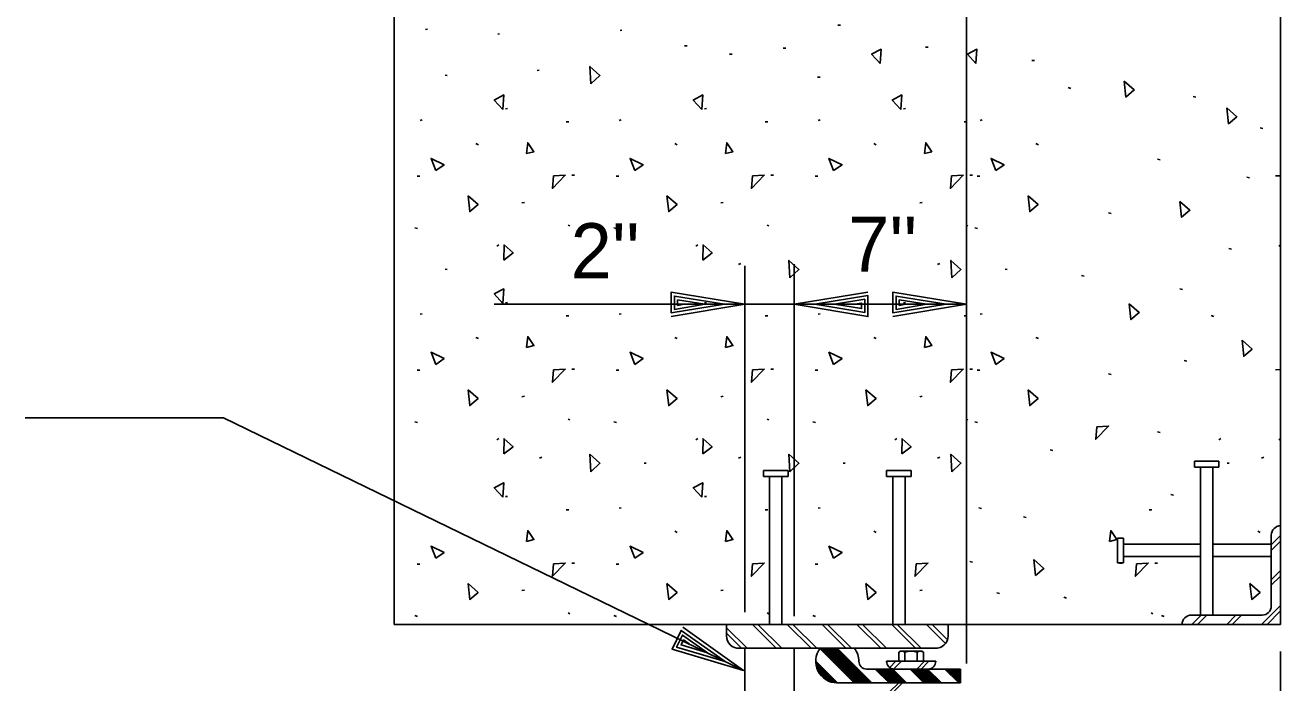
# Model space of a CAD drawing. Extents: x 0 to 53.3, y -2.9 to 37.3.
# Drawn here: x 9.83 to 14.079, y 17.432 to 19.657 of the extents above; entities that cross this region are included whole.
import ezdxf

# ---------------------------------------------------------------- set-up
doc = ezdxf.new("R2010")
doc.units = 0
for name, color, linetype in [('Level 2', 7, 'Continuous'), ('Level 22', 7, 'Continuous'), ('Level 25', 7, 'Continuous'), ('Level 3', 7, 'Continuous'), ('Level 44', 7, 'Continuous'), ('Level 50', 7, 'Continuous')]:
    doc.layers.add(name, color=color, linetype=linetype)

msp = doc.modelspace()

# ---------------------------------------------------------------- linework, layer by layer
at = {"layer": 'Level 2'}
for p, q in [((12.4113, 18.1506), (12.328, 18.1506)), ((12.828, 18.1506), (12.7447, 18.1506)), ((13.8697, 18.1818), (13.7863, 18.1818)), ((13.8697, 18.161), (13.7863, 18.161)), ((12.4113, 18.1298), (12.328, 18.1298)), ((12.828, 18.1298), (12.7447, 18.1298)), ((13.5259, 17.9214), (13.5259, 17.8381)), ((13.5468, 17.9214), (13.5468, 17.8381)), ((14.0155, 17.661), (13.7759, 17.661)), ((14.078, 17.6298), (11.078, 17.6298)), ((12.2655, 17.5489), (12.2655, 17.4006)), ((12.4322, 17.5489), (12.4322, 17.4006)), ((12.7915, 17.5388), (12.7859, 17.5356)), ((12.7859, 17.5049), (12.7859, 17.5356)), ((12.864, 17.5388), (12.7915, 17.5388)), ((12.8068, 17.5357), (12.8068, 17.5049)), ((12.8488, 17.5357), (12.8488, 17.5049)), ((12.864, 17.5388), (12.8696, 17.5356)), ((12.8696, 17.5049), (12.8696, 17.5356)), ((12.9947, 17.4787), (12.677, 17.4787)), ((12.9113, 17.5048), (12.7447, 17.5048)), ((12.7447, 17.5048), (12.7447, 17.5048)), ((12.9113, 17.5048), (12.7447, 17.5048)), ((12.7447, 17.5048), (12.7447, 17.5048)), ((12.8853, 17.4787), (12.7707, 17.4787)), ((12.8696, 17.5049), (12.7859, 17.5049)), ((12.9113, 17.5048), (12.9113, 17.5048)), ((12.9113, 17.5048), (12.9113, 17.5048)), ((12.9947, 17.4318), (12.9947, 17.4787)), ((12.9947, 17.4318), (12.578, 17.4318))]:
    msp.add_line(p, q, dxfattribs=at)
for centre, radius, start, end in [((14.078, 17.9318), 0.0313, 90, 180), ((14.0155, 17.6922), 0.0313, 270, 0), ((13.7759, 17.6297), 0.0313, 90, 180), ((12.2447, 17.5904), 0.0417, 180, 273.1798), ((12.9113, 17.5905), 0.0417, 266.8202, 0), ((12.578, 17.5047), 0.0729, 142.7557, 270.0041), ((12.578, 17.5047), 0.0729, 359.9959, 37.2443), ((12.7965, 17.5207), 0.0182, 55.489, 120.2876), ((12.828, 17.4661), 0.0727, 73.5034, 106.9816), ((12.859, 17.5207), 0.0182, 59.7124, 124.511), ((12.677, 17.5047), 0.026, 180, 270), ((12.7707, 17.5047), 0.026, 180, 270), ((12.8853, 17.5047), 0.026, 270, 0)]:
    msp.add_arc(centre, radius, start, end, dxfattribs=at)
at = {"layer": 'Level 22'}
for p, q in [((9.8296, 18.3281), (10.5009, 18.3281)), ((10.5009, 18.3281), (12.2612, 17.4739))]:
    msp.add_line(p, q, dxfattribs=at)
at = {"layer": 'Level 25'}
msp.add_line((12.909, 17.5489), (12.247, 17.5489), dxfattribs=at)
at = {"layer": 'Level 3'}
for p, q in [((11.078, 21.8798), (11.078, 17.6298)), ((14.078, 20.6298), (14.078, 17.6298)), ((12.328, 18.1506), (12.328, 18.1298)), ((12.4113, 18.1506), (12.4113, 18.1298)), ((12.7447, 18.1506), (12.7447, 18.1298)), ((12.828, 18.1506), (12.828, 18.1298)), ((13.7863, 18.1818), (13.7863, 18.161)), ((13.8072, 18.161), (13.8072, 17.661)), ((13.8488, 18.161), (13.8488, 17.661)), ((13.8697, 18.1818), (13.8697, 18.161)), ((12.3488, 18.1298), (12.3488, 17.6298)), ((12.3905, 18.1298), (12.3905, 17.6298)), ((12.7655, 18.1298), (12.7655, 17.6298)), ((12.8072, 18.1298), (12.8072, 17.6298)), ((13.5259, 17.9214), (13.5468, 17.9214)), ((13.5468, 17.9006), (13.8072, 17.9006)), ((13.8488, 17.9006), (14.0468, 17.9006)), ((14.0468, 17.9318), (14.0468, 17.6923)), ((13.5468, 17.8589), (13.8072, 17.8589)), ((13.8488, 17.8589), (14.0468, 17.8589)), ((13.5259, 17.8381), (13.5468, 17.8381)), ((12.203, 17.6298), (12.203, 17.5905)), ((12.953, 17.6298), (12.953, 17.5905))]:
    msp.add_line(p, q, dxfattribs=at)
for points in [[(14.0468, 17.8985), (14.078, 17.9298)], [(14.0468, 17.8796), (14.078, 17.9109)], [(14.0468, 17.7806), (14.078, 17.8119)], [(14.0468, 17.7618), (14.078, 17.793)], [(14.0137, 17.6298), (14.078, 17.694)], [(13.778, 17.6298), (13.8093, 17.661)], [(13.7968, 17.6298), (13.8281, 17.661)], [(13.8958, 17.6298), (13.9271, 17.661)], [(13.9147, 17.6298), (13.946, 17.661)], [(14.0325, 17.6298), (14.078, 17.6752)], [(12.2726, 17.5489), (12.203, 17.6185)], [(12.2534, 17.5492), (12.203, 17.5996)], [(12.3716, 17.5489), (12.2908, 17.6298)], [(12.3905, 17.5489), (12.3096, 17.6298)], [(12.4895, 17.5489), (12.4086, 17.6298)], [(12.5083, 17.5489), (12.4275, 17.6298)], [(12.6073, 17.5489), (12.5264, 17.6298)], [(12.6262, 17.5489), (12.5453, 17.6298)], [(12.7252, 17.5489), (12.6443, 17.6298)], [(12.7441, 17.5489), (12.6631, 17.6298)], [(12.843, 17.5489), (12.7621, 17.6298)], [(12.8619, 17.5489), (12.781, 17.6298)], [(12.9445, 17.5653), (12.88, 17.6298)], [(12.951, 17.5776), (12.8988, 17.6298)], [(12.6355, 17.4318), (12.5193, 17.548)], [(12.58, 17.5465), (12.5215, 17.5465)], [(12.585, 17.5415), (12.5265, 17.5415)], [(12.59, 17.5365), (12.5315, 17.5365)], [(12.595, 17.5315), (12.5365, 17.5315)], [(12.6, 17.5265), (12.5414, 17.5265)], [(12.605, 17.5215), (12.5464, 17.5215)], [(12.6099, 17.5165), (12.5514, 17.5165)], [(12.6149, 17.5115), (12.5563, 17.5115)], [(12.6945, 17.4318), (12.5775, 17.5489)], [(12.5785, 17.4318), (12.5051, 17.5053)], [(12.5084, 17.5019), (12.5052, 17.5019)], [(12.5133, 17.4969), (12.5053, 17.4969)], [(12.5183, 17.4919), (12.5064, 17.4919)], [(12.5233, 17.4869), (12.5076, 17.4869)], [(12.5283, 17.4819), (12.5094, 17.4819)], [(12.5332, 17.4769), (12.5113, 17.4769)], [(12.5382, 17.4719), (12.5137, 17.4719)], [(12.5431, 17.4669), (12.5163, 17.4669)], [(12.6198, 17.5065), (12.5613, 17.5065)], [(12.6248, 17.5015), (12.5663, 17.5015)], [(12.6298, 17.4965), (12.5713, 17.4965)], [(12.6348, 17.4915), (12.5762, 17.4915)], [(12.6398, 17.4865), (12.5812, 17.4865)], [(12.6448, 17.4815), (12.5861, 17.4815)], [(12.6498, 17.4765), (12.5911, 17.4765)], [(12.6547, 17.4715), (12.5961, 17.4715)], [(12.6597, 17.4665), (12.601, 17.4665)], [(12.7534, 17.4318), (12.7065, 17.4787)], [(12.7695, 17.4747), (12.7107, 17.4747)], [(12.7745, 17.4697), (12.7157, 17.4697)], [(12.7555, 17.4836), (12.7766, 17.5048)], [(12.8123, 17.4318), (12.7655, 17.4787)], [(12.7688, 17.4787), (12.7949, 17.5048)], [(12.8712, 17.4318), (12.8244, 17.4787)], [(12.8837, 17.4785), (12.8249, 17.4785)], [(12.8887, 17.4735), (12.8299, 17.4735)], [(12.8936, 17.4685), (12.8349, 17.4685)], [(12.8469, 17.4787), (12.8729, 17.5048)], [(12.8618, 17.4787), (12.8879, 17.5048)], [(12.9302, 17.4318), (12.8833, 17.4787)], [(12.9891, 17.4318), (12.9423, 17.4787)], [(12.9947, 17.476), (12.9463, 17.476)], [(12.9947, 17.471), (12.9513, 17.471)], [(12.9947, 17.466), (12.9563, 17.466)], [(12.5481, 17.4619), (12.5198, 17.4619)], [(12.553, 17.4569), (12.5233, 17.4569)], [(12.558, 17.4519), (12.5281, 17.4519)], [(12.563, 17.4469), (12.5335, 17.4469)], [(12.568, 17.4419), (12.5406, 17.4419)], [(12.5729, 17.4369), (12.5519, 17.4369)], [(12.5779, 17.4319), (12.5754, 17.4319)], [(12.6647, 17.4615), (12.606, 17.4615)], [(12.6697, 17.4565), (12.6109, 17.4565)], [(12.6746, 17.4515), (12.6159, 17.4515)], [(12.6796, 17.4465), (12.6209, 17.4465)], [(12.6846, 17.4415), (12.6258, 17.4415)], [(12.6896, 17.4365), (12.6308, 17.4365)], [(12.7795, 17.4647), (12.7207, 17.4647)], [(12.7845, 17.4597), (12.7257, 17.4597)], [(12.7894, 17.4547), (12.7306, 17.4547)], [(12.7944, 17.4497), (12.7356, 17.4497)], [(12.7994, 17.4447), (12.7406, 17.4447)], [(12.8044, 17.4397), (12.7456, 17.4397)], [(12.8093, 17.4347), (12.7506, 17.4347)], [(12.755, 17.4011), (12.7862, 17.4324)], [(12.7671, 17.4006), (12.7984, 17.4318)], [(12.8986, 17.4635), (12.8399, 17.4635)], [(12.9036, 17.4585), (12.8449, 17.4585)], [(12.9085, 17.4535), (12.8499, 17.4535)], [(12.9135, 17.4485), (12.8549, 17.4485)], [(12.9185, 17.4435), (12.8598, 17.4435)], [(12.9235, 17.4385), (12.8648, 17.4385)], [(12.9285, 17.4335), (12.8698, 17.4335)], [(12.9947, 17.461), (12.9613, 17.461)], [(12.9947, 17.456), (12.9663, 17.456)], [(12.9947, 17.451), (12.9713, 17.451)], [(12.9947, 17.446), (12.9763, 17.446)], [(12.9947, 17.441), (12.9813, 17.441)], [(12.9947, 17.436), (12.9863, 17.436)]]:
    msp.add_lwpolyline(points, dxfattribs=at)
at = {"layer": 'Level 44'}
for p, q in [((11.1844, 19.642), (11.191, 19.6432)), ((11.8428, 19.6388), (11.8494, 19.64)), ((12.5795, 19.6565), (12.5885, 19.6565)), ((11.4288, 19.6261), (11.4355, 19.6273)), ((12.0615, 19.586), (12.0705, 19.586)), ((12.2136, 19.5578), (12.2226, 19.5578)), ((12.3948, 19.579), (12.4038, 19.579)), ((12.8765, 19.5825), (12.8855, 19.5825)), ((13.2369, 19.5367), (13.2459, 19.5367)), ((11.2509, 19.487), (11.2582, 19.4864)), ((11.5625, 19.5025), (11.5691, 19.5037)), ((12.5107, 19.4803), (12.5197, 19.4803)), ((13.3593, 19.4451), (13.3683, 19.4426)), ((13.7823, 19.4149), (13.7913, 19.4124)), ((11.1667, 19.3345), (11.1734, 19.3357)), ((11.4556, 19.3735), (11.4622, 19.374)), ((11.8401, 19.3345), (11.8467, 19.3357)), ((12.1289, 19.3735), (12.1356, 19.374)), ((12.5134, 19.3345), (12.5201, 19.3357)), ((12.8022, 19.3735), (12.8089, 19.374)), ((13.0617, 19.3345), (13.0684, 19.3357)), ((11.6607, 19.3289), (11.6697, 19.3289)), ((12.3341, 19.3289), (12.3431, 19.3289)), ((13.0074, 19.3289), (13.0164, 19.3289)), ((14.0089, 19.309), (14.0179, 19.3065)), ((11.3554, 19.256), (11.3634, 19.252)), ((12.0287, 19.256), (12.0367, 19.252)), ((12.7021, 19.256), (12.7101, 19.252)), ((13.2504, 19.256), (13.2584, 19.252)), ((13.6614, 19.2031), (13.6704, 19.2006)), ((11.1561, 19.1454), (11.1651, 19.1454)), ((11.6801, 19.1485), (11.6886, 19.1485)), ((11.8294, 19.1454), (11.8384, 19.1454)), ((12.3534, 19.1485), (12.3619, 19.1485)), ((12.5027, 19.1454), (12.5117, 19.1454)), ((13.0267, 19.1485), (13.0352, 19.1485)), ((13.0511, 19.1454), (13.0601, 19.1454)), ((13.9635, 19.1427), (13.9725, 19.1402)), ((11.5104, 19.0554), (11.5191, 19.0569)), ((12.1837, 19.0554), (12.1924, 19.0569)), ((12.8571, 19.0554), (12.8657, 19.0569)), ((13.4953, 19.0217), (13.5043, 19.0192)), ((11.1489, 18.9709), (11.1579, 18.9684)), ((11.6669, 18.9799), (11.6734, 18.9774)), ((11.8222, 18.9709), (11.8312, 18.9684)), ((12.3402, 18.9799), (12.3467, 18.9774)), ((13.0136, 18.9799), (13.0201, 18.9774)), ((13.0439, 18.9709), (13.0529, 18.9684)), ((11.4256, 18.9092), (11.4331, 18.9137)), ((12.0989, 18.9092), (12.1064, 18.9137)), ((14.0717, 18.9092), (14.0792, 18.9137)), ((13.9031, 18.9007), (13.9121, 18.8982)), ((11.2509, 18.8312), (11.2582, 18.8305)), ((12.2441, 18.8472), (12.2512, 18.8505)), ((12.9174, 18.8472), (12.9246, 18.8505)), ((13.1459, 18.8312), (13.1532, 18.8305)), ((13.4046, 18.81), (13.4136, 18.8075)), ((13.737, 18.7646), (13.746, 18.7621)), ((11.4556, 18.7177), (11.4622, 18.7182)), ((12.1289, 18.7177), (12.1356, 18.7182)), ((12.8022, 18.7177), (12.8089, 18.7182)), ((11.1667, 18.6787), (11.1734, 18.6799)), ((11.6607, 18.673), (11.6697, 18.673)), ((11.8401, 18.6787), (11.8467, 18.6799)), ((12.3341, 18.673), (12.3431, 18.673)), ((12.5134, 18.6787), (12.5201, 18.6799)), ((13.0074, 18.673), (13.0164, 18.673)), ((13.0617, 18.6787), (13.0684, 18.6799)), ((13.8427, 18.6739), (13.8517, 18.6714)), ((11.3554, 18.6002), (11.3634, 18.5962)), ((12.0287, 18.6002), (12.0367, 18.5962)), ((12.7021, 18.6002), (12.7101, 18.5962)), ((13.2504, 18.6002), (13.2584, 18.5962)), ((11.1561, 18.4895), (11.1651, 18.4895)), ((11.6801, 18.4927), (11.6886, 18.4927)), ((11.8294, 18.4895), (11.8384, 18.4895)), ((12.3534, 18.4927), (12.3619, 18.4927)), ((12.5027, 18.4895), (12.5117, 18.4895)), ((13.0267, 18.4927), (13.0352, 18.4927)), ((13.0511, 18.4895), (13.0601, 18.4895)), ((13.7521, 18.5226), (13.7611, 18.5201)), ((13.4953, 18.4773), (13.5043, 18.4748)), ((11.5104, 18.3995), (11.5191, 18.401)), ((12.1837, 18.3995), (12.1924, 18.401)), ((12.8571, 18.3995), (12.8657, 18.401)), ((11.6669, 18.324), (11.6734, 18.3215)), ((12.3402, 18.324), (12.3467, 18.3215)), ((13.0136, 18.324), (13.0201, 18.3215)), ((11.1489, 18.315), (11.1579, 18.3125)), ((11.8222, 18.315), (11.8312, 18.3125)), ((12.4956, 18.315), (12.5046, 18.3125)), ((13.0439, 18.315), (13.0529, 18.3125)), ((13.6614, 18.2807), (13.6704, 18.2782)), ((11.4256, 18.2534), (11.4331, 18.2579)), ((12.0989, 18.2534), (12.1064, 18.2579)), ((12.7722, 18.2534), (12.7797, 18.2579)), ((13.8689, 18.2534), (13.8764, 18.2579)), ((14.0717, 18.2534), (14.0792, 18.2579)), ((11.5707, 18.1914), (11.5779, 18.1947)), ((12.2441, 18.1914), (12.2512, 18.1947)), ((12.9174, 18.1914), (12.9246, 18.1947)), ((13.2989, 18.2202), (13.3079, 18.2177)), ((14.0141, 18.1914), (14.0212, 18.1947)), ((11.9242, 18.1754), (11.9316, 18.1747)), ((12.5976, 18.1754), (12.6049, 18.1747)), ((13.897, 18.1754), (13.9043, 18.1747)), ((11.4556, 18.0619), (11.4622, 18.0624)), ((12.1289, 18.0619), (12.1356, 18.0624)), ((13.7068, 18.069), (13.7158, 18.0665)), ((11.8401, 18.0229), (11.8467, 18.024)), ((12.5134, 18.0229), (12.5201, 18.024)), ((13.0572, 18.0236), (13.0662, 18.0211)), ((11.6607, 18.0172), (11.6697, 18.0172)), ((12.3341, 18.0172), (12.3431, 18.0172)), ((13.2083, 17.9934), (13.2173, 17.9909)), ((13.6335, 18.0172), (13.6425, 18.0172)), ((12.0287, 17.9444), (12.0367, 17.9404)), ((12.7021, 17.9444), (12.7101, 17.9404)), ((14.0015, 17.9444), (14.0095, 17.9404)), ((11.1561, 17.8337), (11.1651, 17.8337)), ((11.6801, 17.8369), (11.6886, 17.8369)), ((11.8294, 17.8337), (11.8384, 17.8337)), ((12.5027, 17.8337), (12.5117, 17.8337)), ((13.027, 17.8421), (13.036, 17.8396)), ((13.5334, 17.8369), (13.5419, 17.8369)), ((13.6528, 17.8369), (13.6613, 17.8369)), ((11.5104, 17.7437), (11.5191, 17.7452)), ((12.1837, 17.7437), (12.1924, 17.7452)), ((12.8571, 17.7437), (12.8657, 17.7452)), ((13.1176, 17.7363), (13.1266, 17.7338)), ((13.3442, 17.7212), (13.3532, 17.7187)), ((11.1489, 17.6592), (11.1579, 17.6567)), ((11.6669, 17.6682), (11.6734, 17.6657)), ((11.8222, 17.6592), (11.8312, 17.6567)), ((12.3402, 17.6682), (12.3467, 17.6657)), ((12.4956, 17.6592), (12.5046, 17.6567)), ((13.6397, 17.6682), (13.6462, 17.6657)), ((13.6756, 17.6592), (13.6846, 17.6567))]:
    msp.add_line(p, q, dxfattribs=at)
for points in [[(12.7228, 19.5262), (12.6943, 19.5582), (12.7262, 19.5752)], [(13.047, 19.5262), (13.0185, 19.5582), (13.0504, 19.5752)], [(11.7441, 19.4577), (11.7749, 19.4862), (11.7407, 19.5167)], [(13.5489, 19.4671), (13.583, 19.4372), (13.5547, 19.4134)], [(11.4459, 19.3712), (11.4174, 19.4032), (11.4492, 19.4202)], [(12.1192, 19.3712), (12.0907, 19.4032), (12.1226, 19.4202)], [(12.7926, 19.3712), (12.7641, 19.4032), (12.7959, 19.4202)], [(13.8963, 19.3763), (13.9305, 19.3465), (13.9021, 19.3227)], [(11.5261, 19.2222), (11.5307, 19.2587), (11.5512, 19.2282)], [(12.1994, 19.2222), (12.2041, 19.2587), (12.2246, 19.2282)], [(12.8727, 19.2222), (12.8774, 19.2587), (12.8979, 19.2282)], [(11.2191, 19.1649), (11.2032, 19.2057), (11.2474, 19.1842)], [(11.8924, 19.1649), (11.8766, 19.2057), (11.9207, 19.1842)], [(12.5657, 19.1649), (12.5499, 19.2057), (12.5941, 19.1842)], [(13.1141, 19.1649), (13.0982, 19.2057), (13.1424, 19.1842)], [(11.6176, 19.1464), (11.6576, 19.1485), (11.6142, 19.1042)], [(12.2909, 19.1464), (12.3309, 19.1485), (12.2876, 19.1042)], [(12.9642, 19.1464), (13.0042, 19.1485), (12.9609, 19.1042)], [(11.3284, 19.0794), (11.3626, 19.0495), (11.3342, 19.0257)], [(12.0017, 19.0794), (12.0359, 19.0495), (12.0076, 19.0257)], [(13.2234, 19.0794), (13.2576, 19.0495), (13.2292, 19.0257)], [(13.737, 19.0601), (13.7712, 19.0303), (13.7429, 19.0065)], [(11.4492, 18.862), (11.4812, 18.8862), (11.4506, 18.9134)], [(12.1226, 18.862), (12.1546, 18.8862), (12.1239, 18.9134)], [(12.4174, 18.8019), (12.4482, 18.8304), (12.4141, 18.8609)], [(12.9657, 18.8019), (12.9966, 18.8304), (12.9624, 18.8609)], [(11.4459, 18.7154), (11.4174, 18.7474), (11.4492, 18.7644)], [(13.5658, 18.714), (13.6, 18.6842), (13.5717, 18.6603)], [(11.5261, 18.5664), (11.5307, 18.6029), (11.5512, 18.5724)], [(12.1994, 18.5664), (12.2041, 18.6029), (12.2246, 18.5724)], [(12.8727, 18.5664), (12.8774, 18.6029), (12.8979, 18.5724)], [(13.9478, 18.5904), (13.9819, 18.5606), (13.9536, 18.5367)], [(11.2191, 18.509), (11.2032, 18.5499), (11.2474, 18.5284)], [(11.8924, 18.509), (11.8766, 18.5499), (11.9207, 18.5284)], [(12.5657, 18.509), (12.5499, 18.5499), (12.5941, 18.5284)], [(13.1141, 18.509), (13.0982, 18.5499), (13.1424, 18.5284)], [(11.6176, 18.4905), (11.6576, 18.4927), (11.6142, 18.4484)], [(12.2909, 18.4905), (12.3309, 18.4927), (12.2876, 18.4484)], [(12.9642, 18.4905), (13.0042, 18.4927), (12.9609, 18.4484)], [(11.3284, 18.4235), (11.3626, 18.3937), (11.3342, 18.3699)], [(12.0017, 18.4235), (12.0359, 18.3937), (12.0076, 18.3699)], [(12.6751, 18.4235), (12.7092, 18.3937), (12.6809, 18.3699)], [(13.2234, 18.4235), (13.2576, 18.3937), (13.2292, 18.3699)], [(13.456, 18.2983), (13.496, 18.3004), (13.4527, 18.2561)], [(11.4492, 18.2062), (11.4812, 18.2304), (11.4506, 18.2575)], [(12.1226, 18.2062), (12.1546, 18.2304), (12.1239, 18.2575)], [(12.7959, 18.2062), (12.8279, 18.2304), (12.7972, 18.2575)], [(11.7441, 18.146), (11.7749, 18.1745), (11.7407, 18.205)], [(12.4174, 18.146), (12.4482, 18.1745), (12.4141, 18.205)], [(12.9657, 18.146), (12.9966, 18.1745), (12.9624, 18.205)], [(11.4459, 18.0595), (11.4174, 18.0915), (11.4492, 18.1085)], [(12.1192, 18.0595), (12.0907, 18.0915), (12.1226, 18.1085)], [(11.5261, 17.9105), (11.5307, 17.947), (11.5512, 17.9165)], [(12.1994, 17.9105), (12.2041, 17.947), (12.2246, 17.9165)], [(13.4988, 17.9105), (13.5035, 17.947), (13.524, 17.9165)], [(11.2191, 17.8532), (11.2032, 17.894), (11.2474, 17.8725)], [(11.8924, 17.8532), (11.8766, 17.894), (11.9207, 17.8725)], [(12.5657, 17.8532), (12.5499, 17.894), (12.5941, 17.8725)], [(13.2431, 17.8487), (13.2773, 17.8189), (13.249, 17.7951)], [(11.6176, 17.8347), (11.6576, 17.8369), (11.6142, 17.7925)], [(12.2909, 17.8347), (12.3309, 17.8369), (12.2876, 17.7925)], [(12.8448, 17.8347), (12.8848, 17.8369), (12.8414, 17.7925)], [(13.5903, 17.8347), (13.6303, 17.8369), (13.587, 17.7925)], [(11.3284, 17.7677), (11.3626, 17.7379), (11.3342, 17.714)], [(12.0017, 17.7677), (12.0359, 17.7379), (12.0076, 17.714)], [(12.6751, 17.7677), (12.7092, 17.7379), (12.6809, 17.714)], [(13.9745, 17.7677), (14.0087, 17.7379), (13.9803, 17.714)]]:
    msp.add_lwpolyline(points, close=True, dxfattribs=at)
for points in [[(14.0609, 19.1464), (14.078, 19.1473)], [(14.0609, 18.4905), (14.078, 18.4915)]]:
    msp.add_lwpolyline(points, dxfattribs=at)
at = {"layer": 'Level 50'}
for p, q in [((13.0155, 17.4978), (13.0155, 21.1768)), ((12.2655, 17.6711), (12.2655, 18.8426)), ((12.4322, 17.6578), (12.4322, 18.8485)), ((12.2655, 18.7123), (11.4165, 18.7123)), ((12.1962, 18.7123), (12.1962, 18.7123)), ((12.4322, 18.7123), (12.2655, 18.7123)), ((12.2655, 18.7123), (12.2655, 18.7123)), ((13.0155, 18.7123), (12.4322, 18.7123)), ((12.4322, 18.7123), (12.4322, 18.7123)), ((12.5015, 18.7123), (12.5015, 18.7123)), ((12.9462, 18.7123), (12.9462, 18.7123)), ((13.0155, 18.7123), (13.0155, 18.7123)), ((14.078, 17.5383), (14.078, 12.904)), ((12.1988, 17.5042), (12.1988, 17.5042)), ((12.2612, 17.4739), (12.2612, 17.4739))]:
    msp.add_line(p, q, dxfattribs=at)
for points in [[(12.0162, 18.6709), (12.2655, 18.7123), (12.0162, 18.7536), (12.0162, 18.6829), (12.1962, 18.7123), (12.0268, 18.7403), (12.0268, 18.6949), (12.1295, 18.7123), (12.0375, 18.7269), (12.0375, 18.7083), (12.0602, 18.7123)], [(12.6815, 18.7536), (12.4322, 18.7123), (12.6815, 18.6709), (12.6815, 18.7416), (12.5015, 18.7123), (12.6708, 18.6843), (12.6708, 18.7296), (12.5682, 18.7123), (12.6602, 18.6976), (12.6602, 18.7163), (12.6375, 18.7123)], [(12.7662, 18.6709), (13.0155, 18.7123), (12.7662, 18.7536), (12.7662, 18.6829), (12.9462, 18.7123), (12.7768, 18.7403), (12.7768, 18.6949), (12.8795, 18.7123), (12.7875, 18.7269), (12.7875, 18.7083), (12.8102, 18.7123)], [(12.0549, 17.62), (12.2612, 17.4739), (12.0188, 17.5456), (12.0497, 17.6092), (12.1988, 17.5042), (12.0343, 17.5529), (12.054, 17.5937), (12.1388, 17.5333), (12.0497, 17.5603), (12.0578, 17.5771), (12.0765, 17.5636)]]:
    msp.add_lwpolyline(points, dxfattribs=at)

# ---------------------------------------------------------------- texts
for s, p in [("7''", (12.615, 18.8222)), ("2''", (11.676, 18.7998))]:
    msp.add_text(s, height=0.1867, dxfattribs=at).set_placement(p)

doc.saveas('drawing.dxf')
